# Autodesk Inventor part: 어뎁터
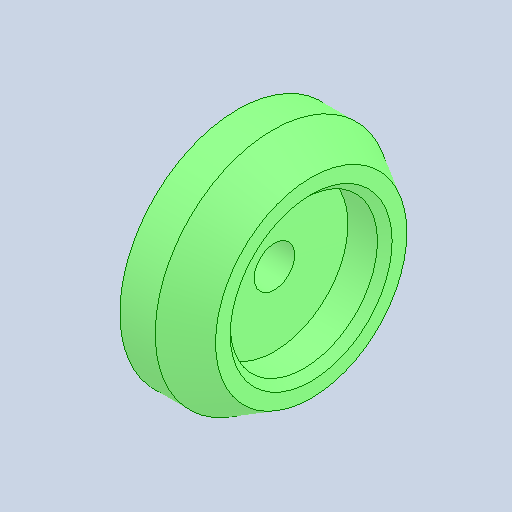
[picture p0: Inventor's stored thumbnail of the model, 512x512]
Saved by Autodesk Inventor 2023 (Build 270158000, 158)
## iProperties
Created: 2024-09
Part Number: 어뎁터
Material: 강철, 탄소
Document SubType Name: Modeling
Designer: home
Density: 7.85 g/cm^3
Appearance: 기본값
Author: jhkim
Sending System: Autodesk Inventor 2025
Preprocessor: ST-DEVELOPER v20
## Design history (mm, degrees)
feature "솔리드1"
node "솔리드2"
